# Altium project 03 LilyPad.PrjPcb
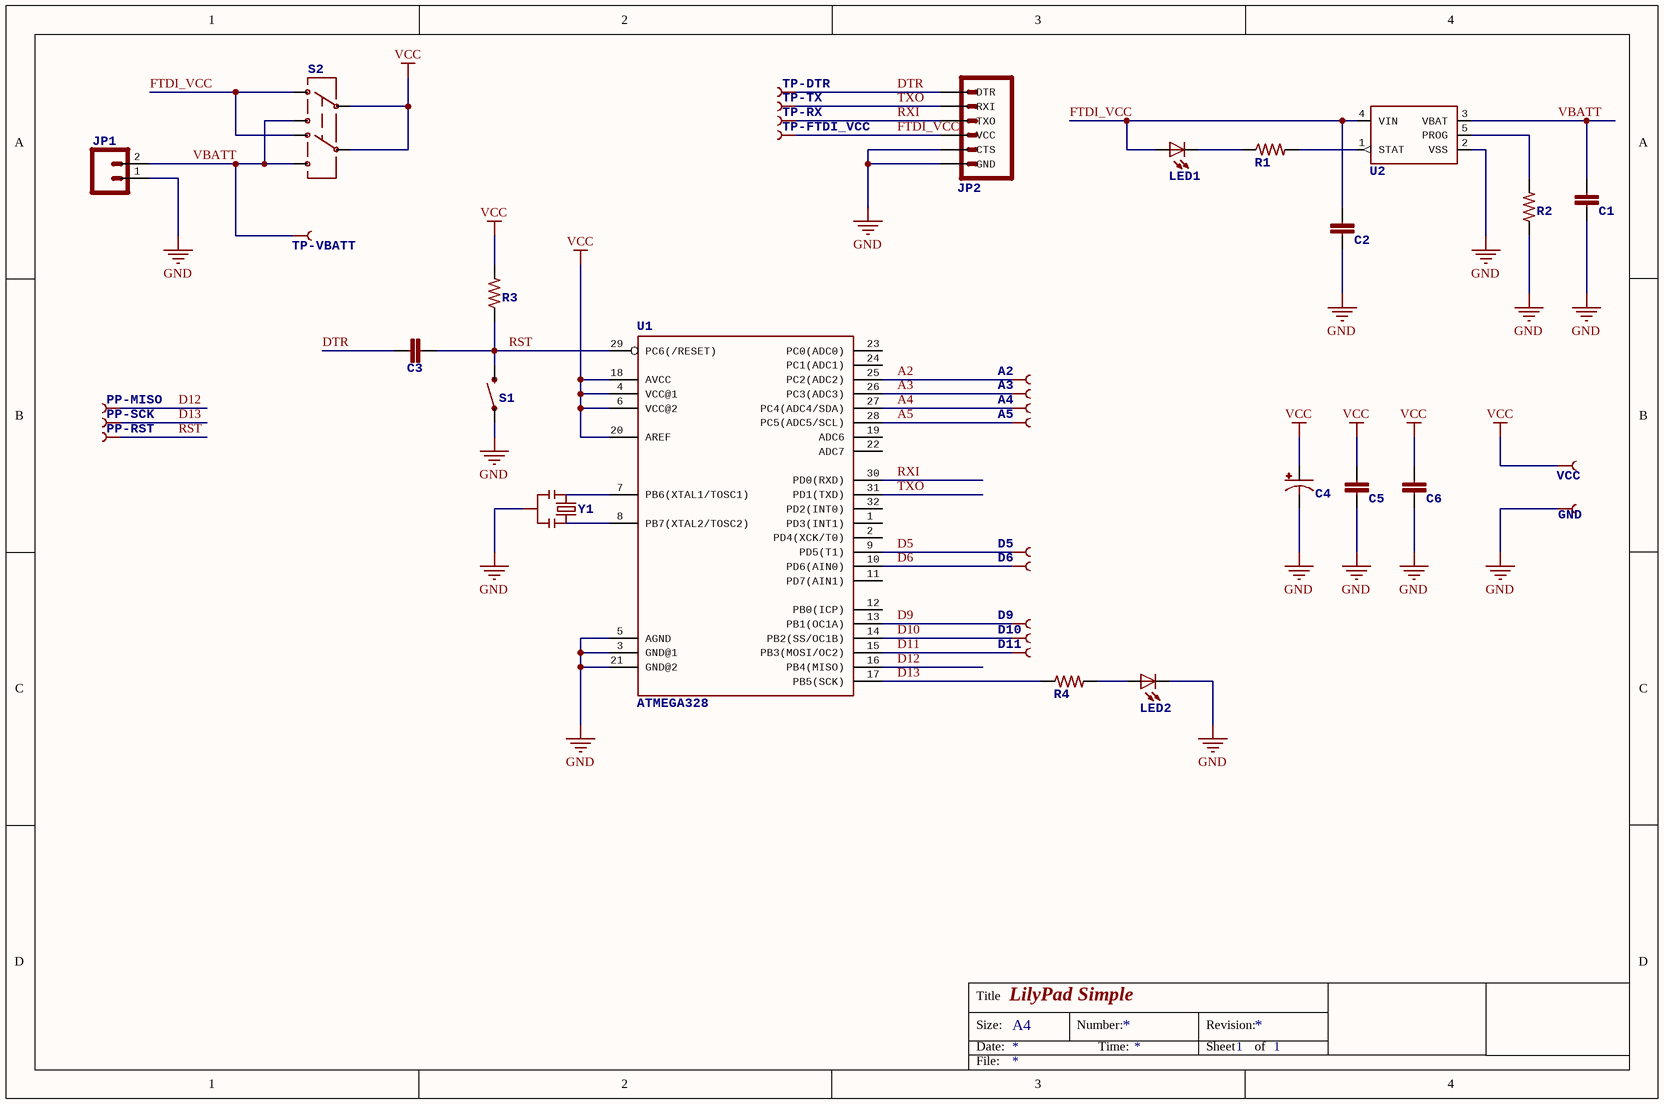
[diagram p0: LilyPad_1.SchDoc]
1 sheet, 38 parts. Net scope: global (net labels, ports and power ports of the same name join across sheets).

## Sheet LilyPad_1.SchDoc: LilyPad Simple
size A4; SheetNumber: 1; SheetTotal: 1

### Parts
A2  CONN  [PETAL-LONG-2]  (value not drawn)
A3  CONN  [PETAL-LONG-2]  (value not drawn)
A4  CONN  [PETAL-LONG-2]  (value not drawn)
A5  CONN  [PETAL-LONG-2]  (value not drawn)
C1  CAP0402-CAP  [0402-CAP]  (value not drawn)
C2  CAP0402-CAP  [0402-CAP]  (value not drawn)
C3  CAP0402-CAP  [0402-CAP]  (value not drawn)
C4  CAP_POL3528  [EIA3528]  (value not drawn)
C5  CAP0402-CAP  [0402-CAP]  (value not drawn)
C6  CAP0402-CAP  [0402-CAP]  (value not drawn)
D5  CONN  [PETAL-LONG-2]  (value not drawn)
D6  CONN  [PETAL-LONG-2]  (value not drawn)
D9  CONN  [PETAL-LONG-2]  (value not drawn)
D10  CONN  [PETAL-LONG-2]  (value not drawn)
D11  CONN  [PETAL-LONG-2]  (value not drawn)
GND  CONN  [PETAL-LONG-2]  (value not drawn)
JP1  M02-JST-2MM-SMT  [JST-2-SMD]  (value not drawn)
JP2  ARDUINO_SERIAL_PROGRAMSMD  [1X06-SMD]  (value not drawn)
LED1  LED0603  [LED-0603]  (value not drawn)
LED2  LED0603  [LED-0603]  (value not drawn)
PP-MISO  TEST-POINT3X5  [PAD.03X.05]  (value not drawn)
PP-RST  TEST-POINT3X5  [PAD.03X.05]  (value not drawn)
PP-SCK  TEST-POINT3X5  [PAD.03X.05]  (value not drawn)
R1  RESISTOR0402-RES  [0402-RES]  (value not drawn)
R2  RESISTOR0402-RES  [0402-RES]  (value not drawn)
R3  RESISTOR0402-RES  [0402-RES]  (value not drawn)
R4  RESISTOR0402-RES  [0402-RES]  (value not drawn)
S1  SWITCH-MOMENTARY-2SMD-2  [TACTILE_SWITCH_SMD-2]  (value not drawn)
S2  AYZ0202  [AYZ0202]  (value not drawn)
TP-DTR  TEST-POINT3X5  [PAD.03X.05]  (value not drawn)
TP-FTDI_VCC  TEST-POINT3X5  [PAD.03X.05]  (value not drawn)
TP-RX  TEST-POINT3X5  [PAD.03X.05]  (value not drawn)
TP-TX  TEST-POINT3X5  [PAD.03X.05]  (value not drawn)
TP-VBATT  TEST-POINT3X5  [PAD.03X.05]  (value not drawn)
U1  ATMEGA328  [TQFP32-08]
U2  MCP73831  [SOT23-5]  (value not drawn)
VCC  CONN  [PETAL-LONG-2]  (value not drawn)
Y1  RESONATORSMD  [RESONATOR-SMD]  (value not drawn)

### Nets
GND: C1.2 C2.2 C4.C(-) C5.2 C6.2 GND.1 JP1.1 JP2.5(CTS) JP2.6(GND) LED2.C R2.1 S1.2 U1.3(GND@1) U1.5(AGND) U1.21(GND@2) U2.2(VSS) Y1.2
VCC: C4.A(+) C5.1 C6.1 R3.2 S2.2 S2.5 U1.4(VCC@1) U1.6(VCC@2) U1.18(AVCC) U1.20(AREF) VCC.1
A2: A2.1 U1.25(PC2(ADC2))
A3: A3.1 U1.26(PC3(ADC3))
A4: A4.1 U1.27(PC4(ADC4/SDA))
A5: A5.1 U1.28(PC5(ADC5/SCL))
D5: D5.1 U1.9(PD5(T1))
D6: D6.1 U1.10(PD6(AIN0))
D9: D9.1 U1.13(PB1(OC1A))
D10: D10.1 U1.14(PB2(SS/OC1B))
D11: D11.1 U1.15(PB3(MOSI/OC2))
D12: PP-MISO.P$1 U1.16(PB4(MISO))
D13: PP-SCK.P$1 R4.1 U1.17(PB5(SCK))
DTR: C3.1 JP2.1(DTR) TP-DTR.P$1
FTDI_VCC: C2.1 JP2.4(VCC) LED1.A S2.3 S2.6 TP-FTDI_VCC.P$1 U2.4(VIN)
RST: C3.2 PP-RST.P$1 R3.1 S1.1 U1.29(PC6(/RESET))
RXI: JP2.3(TXO) TP-RX.P$1 U1.30(PD0(RXD))
TXO: JP2.2(RXI) TP-TX.P$1 U1.31(PD1(TXD))
VBATT: C1.1 JP1.2 S2.1 S2.4 TP-VBATT.P$1 U2.3(VBAT)
NetLED1_C: LED1.C R1.1
NetLED2_A: LED2.A R4.2
NetR1_2: R1.2 U2.1(STAT)
NetR2_2: R2.2 U2.5(PROG)
NetU1_7: U1.7(PB6(XTAL1/TOSC1)) Y1.1
NetU1_8: U1.8(PB7(XTAL2/TOSC2)) Y1.3

Not connected (* = marked no-connect by the designer): U1 1(PD3(INT1)) 2(PD4(XCK/T0)) 11(PD7(AIN1)) 12(PB0(ICP)) 19(ADC6) 22(ADC7) 23(PC0(ADC0)) 24(PC1(ADC1)) 32(PD2(INT0))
